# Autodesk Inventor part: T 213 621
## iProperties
Created: 2005-10
Part Number: T 213 621
Material: Durethan BKV30H
Document SubType Name: Modeling
Designer: I.Baliuc
Manufacturer: Standard
Standards Organization: Custom
Description: Isolator
Density: 0.94 g/cm^3
Title: Isolator
Company: Mayer & Müller AG Schaltgeräte
Author: T.Messerschmitt
Revision Number: 213621
Keywords: 213600
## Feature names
1. Extrusion8
2. Bohrung_Ø6.2 [Hole]
3. Bohrung_Ø8 [Hole]
4. Bezeichnung2 [Tagging]
